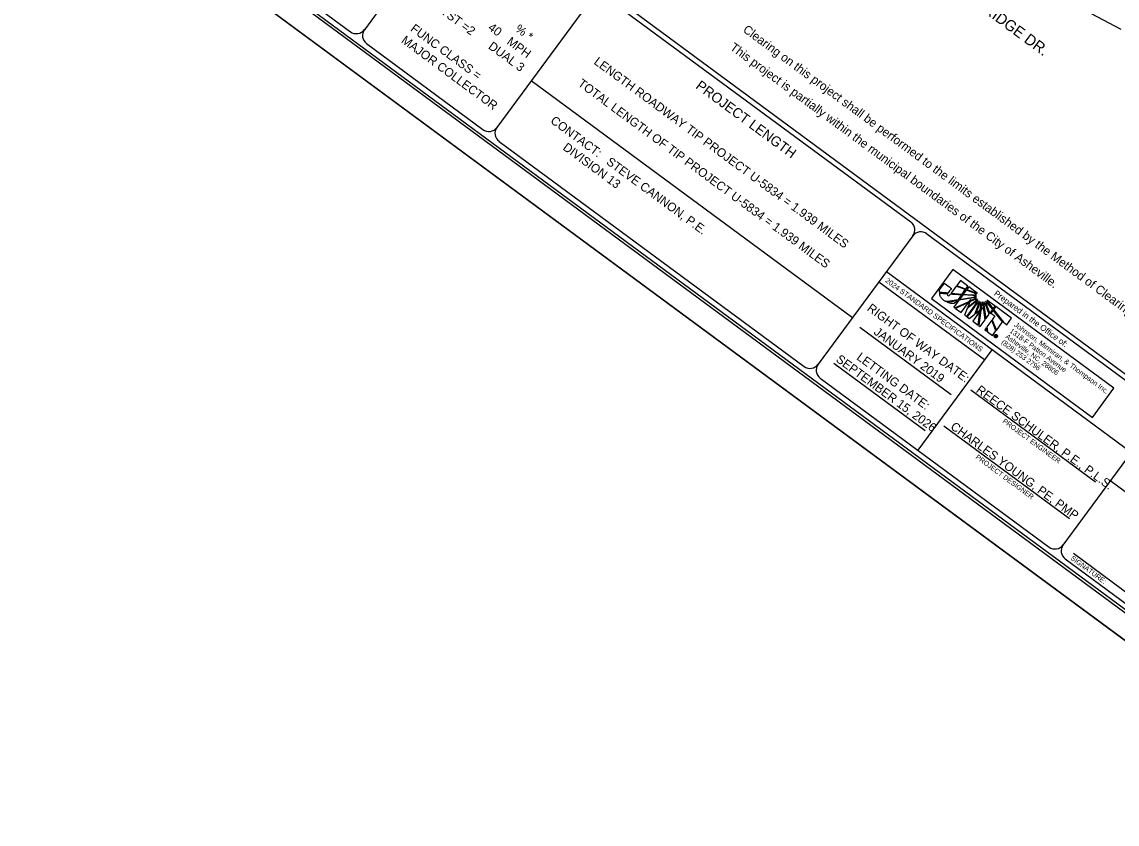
# Model space of a CAD drawing. Extents: x 945666 to 965748, y 644452 to 663300.
# Drawn here: x 945666 to 956642, y 644452 to 652491 of the extents above; entities that cross this region are included whole.
import ezdxf

# ---------------------------------------------------------------- set-up
doc = ezdxf.new("R2010")
doc.units = 0
for name, color, linetype in [('Default', 7, 'Continuous'), ('Old_Level_23', 7, 'Continuous'), ('Sheet Cutting Line CELL', 7, 'Continuous'), ('Sheet Data Field CELL', 7, 'Continuous'), ('Sheet Plan Layout CELL', 7, 'Continuous'), ('Sheet Plot Border Inside CELL', 7, 'Continuous'), ('Sheet Plot Border Outside CELL', 7, 'Continuous'), ('Sheet Title CELL', 7, 'Continuous')]:
    doc.layers.add(name, color=color, linetype=linetype)

msp = doc.modelspace()

# ---------------------------------------------------------------- linework, layer by layer
at = {"layer": 'Default'}
for p, q in [((955071, 649898), (955035, 649848)), ((955147, 649842), (955071, 649898)), ((955030, 649842), (954978, 649772)), ((955121, 649808), (955030, 649842)), ((955035, 649848), (955125, 649813)), ((955089, 649764), (955121, 649808)), ((955131, 649804), (955101, 649763)), ((955125, 649813), (955147, 649842)), ((955207, 649775), (955131, 649804)), ((955155, 649837), (955135, 649810)), ((955135, 649810), (955211, 649781)), ((955240, 649774), (955155, 649837)), ((955234, 649760), (955207, 649775)), ((955211, 649781), (955240, 649774)), ((954978, 649772), (955089, 649764)), ((955055, 649702), (955005, 649633)), ((955017, 649624), (955161, 649690)), ((955153, 649679), (955023, 649620)), ((955202, 649727), (955055, 649702)), ((955096, 649757), (955061, 649710)), ((955061, 649710), (955202, 649734)), ((955080, 649578), (955153, 649679)), ((955192, 649750), (955096, 649757)), ((955101, 649763), (955184, 649757)), ((955221, 649684), (955140, 649618)), ((955145, 649631), (955220, 649692)), ((955166, 649685), (955145, 649631)), ((955161, 649690), (955176, 649710)), ((955210, 649705), (955166, 649685)), ((955169, 649693), (955207, 649711)), ((955176, 649710), (955169, 649693)), ((955184, 649757), (955234, 649760)), ((955232, 649744), (955192, 649750)), ((955202, 649734), (955232, 649744)), ((955234, 649728), (955202, 649727)), ((955207, 649711), (955234, 649728)), ((955209, 649639), (955249, 649701)), ((955239, 649713), (955210, 649705)), ((955262, 649692), (955214, 649635)), ((955220, 649692), (955239, 649713)), ((955249, 649701), (955221, 649684)), ((955254, 649660), (955262, 649692)), ((955276, 649686), (955261, 649660)), ((955277, 649656), (955276, 649686)), ((955292, 649685), (955284, 649654)), ((955301, 649655), (955292, 649685)), ((955308, 649687), (955307, 649656)), ((955326, 649651), (955308, 649687)), ((955323, 649694), (955335, 649645)), ((955344, 649674), (955323, 649694)), ((955420, 649642), (955336, 649704)), ((955336, 649704), (955350, 649678)), ((955396, 649609), (955344, 649674)), ((955350, 649678), (955400, 649614)), ((955005, 649633), (955017, 649624)), ((955023, 649620), (955080, 649578)), ((955140, 649618), (955114, 649553)), ((955135, 649538), (955209, 649639)), ((955214, 649635), (955140, 649534)), ((955161, 649519), (955215, 649561)), ((955268, 649591), (955196, 649493)), ((955215, 649561), (955254, 649660)), ((955261, 649660), (955225, 649569)), ((955225, 649569), (955270, 649606)), ((955250, 649453), (955268, 649591)), ((955276, 649602), (955256, 649448)), ((955270, 649606), (955277, 649656)), ((955293, 649624), (955276, 649602)), ((955284, 649654), (955278, 649612)), ((955278, 649612), (955293, 649624)), ((955319, 649506), (955301, 649655)), ((955307, 649656), (955325, 649514)), ((955325, 649514), (955361, 649562)), ((955361, 649562), (955326, 649651)), ((955335, 649645), (955366, 649569)), ((955366, 649569), (955396, 649609)), ((955400, 649603), (955378, 649572)), ((955378, 649572), (955417, 649544)), ((955400, 649614), (955420, 649642)), ((955401, 649603), (955400, 649603)), ((955493, 649484), (955401, 649603)), ((955426, 649638), (955404, 649609)), ((955404, 649609), (955404, 649608)), ((955404, 649608), (955503, 649481)), ((955585, 649521), (955426, 649638)), ((955114, 649553), (955135, 649538)), ((955140, 649534), (955161, 649519)), ((955196, 649493), (955250, 649453)), ((955256, 649448), (955269, 649438)), ((955269, 649438), (955319, 649506)), ((955385, 649501), (955336, 649434)), ((955427, 649394), (955385, 649501)), ((955417, 649544), (955390, 649507)), ((955390, 649507), (955432, 649400)), ((955432, 649400), (955493, 649484)), ((955503, 649481), (955537, 649456)), ((955537, 649456), (955585, 649521)), ((955330, 649426), (955315, 649405)), ((955315, 649405), (955334, 649391)), ((955334, 649391), (955330, 649426)), ((955336, 649434), (955342, 649385)), ((955342, 649385), (955393, 649347)), ((955393, 649347), (955427, 649394)), ((955418, 649340), (955426, 649352)), ((955421, 649338), (955418, 649340)), ((955424, 649343), (955421, 649338)), ((955426, 649341), (955424, 649343)), ((955427, 649347), (955425, 649345)), ((955425, 649345), (955428, 649343)), ((955426, 649352), (955431, 649348)), ((955428, 649343), (955426, 649341)), ((955426, 649341), (955428, 649343)), ((955426, 649341), (955426, 649341)), ((955430, 649346), (955427, 649347)), ((955428, 649343), (955428, 649343)), ((955431, 649348), (955430, 649346)), ((955430, 649346), (955431, 649348)), ((955430, 649346), (955430, 649346)), ((955431, 649348), (955432, 649348)), ((955436, 649355), (955434, 649352)), ((955434, 649352), (955436, 649355)), ((955419, 649332), (955417, 649329)), ((955417, 649329), (955419, 649332)), ((955418, 649329), (955417, 649329)), ((955419, 649332), (955419, 649332))]:
    msp.add_line(p, q, dxfattribs=at)
msp.add_lwpolyline([(954781, 649718), (956394, 648528), (956609, 648819), (954996, 650009)], close=True, dxfattribs=at)
for points in [[(955035, 649848), (955125, 649813), (955147, 649842), (955071, 649898), (955035, 649848)], [(954978, 649772), (955089, 649764), (955121, 649808), (955030, 649842), (954978, 649772)], [(955131, 649804), (955101, 649763), (955184, 649757), (955234, 649760), (955207, 649775), (955131, 649804)], [(955211, 649781), (955240, 649774), (955155, 649837), (955135, 649810), (955211, 649781)], [(955234, 649728), (955202, 649727), (955055, 649702), (955005, 649633), (955017, 649624), (955161, 649690), (955176, 649710), (955169, 649693), (955207, 649711), (955234, 649728)], [(955023, 649620), (955080, 649578), (955153, 649679), (955023, 649620)], [(955096, 649757), (955061, 649710), (955202, 649734), (955232, 649744), (955192, 649750), (955096, 649757)], [(955221, 649684), (955140, 649618), (955114, 649553), (955135, 649538), (955209, 649639), (955249, 649701), (955221, 649684)], [(955262, 649692), (955214, 649635), (955140, 649534), (955161, 649519), (955215, 649561), (955254, 649660), (955262, 649692)], [(955239, 649713), (955210, 649705), (955166, 649685), (955145, 649631), (955220, 649692), (955239, 649713)], [(955276, 649686), (955261, 649660), (955225, 649569), (955270, 649606), (955277, 649656), (955276, 649686)], [(955292, 649685), (955284, 649654), (955278, 649612), (955293, 649624), (955276, 649602), (955256, 649448), (955269, 649438), (955319, 649506), (955301, 649655), (955292, 649685)], [(955308, 649687), (955307, 649656), (955325, 649514), (955361, 649562), (955326, 649651), (955308, 649687)], [(955323, 649694), (955335, 649645), (955366, 649569), (955396, 649609), (955344, 649674), (955323, 649694)], [(955350, 649678), (955400, 649614), (955420, 649642), (955336, 649704), (955350, 649678)], [(955196, 649493), (955250, 649453), (955268, 649591), (955196, 649493)], [(955401, 649603), (955400, 649603), (955378, 649572), (955417, 649544), (955390, 649507), (955432, 649400), (955493, 649484), (955401, 649603)], [(955585, 649521), (955426, 649638), (955404, 649609), (955404, 649608), (955503, 649481), (955537, 649456), (955585, 649521)], [(955385, 649501), (955336, 649434), (955342, 649385), (955393, 649347), (955427, 649394), (955385, 649501), (955385, 649501)], [(955315, 649405), (955315, 649405), (955334, 649391), (955330, 649426), (955315, 649405)], [(955430, 649336), (955429, 649335), (955429, 649334), (955429, 649334), (955428, 649332), (955426, 649334)]]:
    msp.add_lwpolyline(points, dxfattribs=at)
for points, degree in [([(954981, 649820), (954981, 649820), (954911, 649872), (954911, 649872), (954911, 649872), (954879, 649828), (954879, 649828), (954879, 649828), (954875, 649823), (954875, 649823), (954865, 649810), (954862, 649795), (954863, 649780), (954863, 649780), (954946, 649773), (954947, 649774), (954947, 649774), (954981, 649820), (954981, 649820)], 3), ([(954945, 649749), (954941, 649753), (954939, 649758), (954943, 649767), (954943, 649767), (954864, 649774), (954864, 649774), (954868, 649744), (954887, 649714), (954910, 649697), (954915, 649693), (954920, 649690), (954927, 649687), (954927, 649687), (955047, 649707), (955047, 649707), (955047, 649707), (955085, 649758), (955085, 649758), (955085, 649758), (954974, 649765), (954974, 649765), (954960, 649746), (954951, 649745), (954945, 649749)], 3), ([(954945, 649749), (954941, 649753), (954939, 649758), (954943, 649767), (954943, 649767), (954864, 649774), (954864, 649774), (954868, 649744), (954887, 649714), (954910, 649697), (954915, 649693), (954920, 649690), (954927, 649687), (954927, 649687), (955047, 649707), (955047, 649707), (955047, 649707), (955085, 649758), (955085, 649758), (955085, 649758), (954974, 649765), (954974, 649765), (954960, 649746), (954951, 649745), (954945, 649749)], 3), ([(955041, 649699), (955041, 649699), (954938, 649682), (954938, 649682), (954972, 649668), (955015, 649665), (955041, 649699)], 3), ([(955417, 649329), (955414, 649332), (955412, 649336), (955411, 649340), (955410, 649344), (955411, 649348), (955414, 649352), (955417, 649355), (955420, 649357), (955424, 649358), (955429, 649358), (955433, 649358), (955436, 649355)], 3), ([(955434, 649352), (955432, 649355), (955428, 649355), (955425, 649355), (955422, 649354), (955419, 649353), (955417, 649350), (955415, 649347), (955414, 649344), (955414, 649340), (955415, 649337), (955417, 649334), (955419, 649332)], 3), ([(955419, 649332), (955422, 649330), (955425, 649329), (955429, 649330), (955432, 649330), (955435, 649332), (955437, 649335), (955439, 649337), (955440, 649341), (955440, 649344), (955439, 649348), (955437, 649350), (955434, 649352)], 3), ([(955428, 649339), (955428, 649339), (955427, 649340), (955426, 649341)], 2), ([(955426, 649334), (955426, 649335), (955426, 649336), (955427, 649337), (955428, 649338), (955428, 649339), (955428, 649339)], 3), ([(955428, 649343), (955429, 649342), (955431, 649342), (955431, 649343), (955432, 649343), (955431, 649344), (955430, 649346)], 3), ([(955431, 649339), (955431, 649338), (955431, 649337), (955430, 649336)], 2), ([(955432, 649348), (955435, 649345), (955435, 649343), (955434, 649341), (955433, 649340), (955432, 649339), (955431, 649339)], 3), ([(955436, 649355), (955440, 649352), (955442, 649349), (955443, 649344), (955443, 649340), (955442, 649336), (955440, 649333)], 3), ([(955440, 649333), (955437, 649329), (955434, 649327), (955429, 649326), (955425, 649326), (955421, 649327), (955418, 649329)], 3)]:
    msp.add_open_spline(points, degree=degree, dxfattribs=at)
at = {"layer": 'Sheet Cutting Line CELL'}
msp.add_line((945666, 654448), (959219, 644452), dxfattribs=at)
at = {"layer": 'Sheet Plan Layout CELL'}
msp.add_line((955894, 652835), (956681, 652419), dxfattribs=at)
at = {"layer": 'Sheet Plot Border Inside CELL'}
msp.add_lwpolyline([(945904, 654551), (959316, 644660), (965578, 653151), (952166, 663042)], close=True, dxfattribs=at)
at = {"layer": 'Sheet Plot Border Outside CELL'}
msp.add_lwpolyline([(965748, 653305), (952195, 663300), (945666, 654448), (959219, 644452)], close=True, dxfattribs=at)
at = {"layer": 'Sheet Title CELL'}
for p, q in [((948809, 654801), (960237, 646372)), ((950048, 653701), (949098, 652413)), ((951516, 652742), (954574, 650487)), ((951376, 652721), (950426, 651434)), ((953990, 649526), (950770, 651900)), ((954595, 650347), (953646, 649060)), ((954735, 650368), (957029, 648677)), ((955313, 649104), (954254, 649884)), ((956784, 648177), (954330, 649987)), ((954980, 648754), (954065, 649429)), ((955008, 649329), (955008, 649329)), ((955388, 649206), (954645, 648198)), ((954719, 648393), (953804, 649068)), ((954522, 649092), (954522, 649092)), ((955177, 648803), (956425, 647882)), ((956100, 647249), (957050, 648537)), ((954907, 648443), (956164, 647516)), ((956568, 647899), (958344, 646589)), ((956204, 647166), (957342, 646326))]:
    msp.add_line(p, q, dxfattribs=at)
for points in [[(947239, 653598), (959150, 644814)], [(947711, 653312), (948959, 652392)], [(949120, 652273), (950287, 651413)], [(950448, 651294), (953506, 649038)], [(953667, 648920), (955960, 647228)], [(956121, 647109), (957729, 645924)]]:
    msp.add_lwpolyline(points, dxfattribs=at)
for centre, start, end in [((949018, 652473), 233.5908, 323.5908), ((949179, 652354), 143.5908, 233.5908), ((950346, 651493), 233.5908, 323.5908), ((950507, 651375), 143.5908, 233.5908), ((954515, 650407), 323.5908, 53.5908), ((954676, 650288), 53.5908, 143.5908), ((953565, 649119), 233.5908, 323.5908), ((953726, 649001), 143.5908, 233.5908), ((956020, 647309), 233.5908, 323.5908), ((956181, 647190), 143.5908, 233.5908)]:
    msp.add_arc(centre, 100, start, end, dxfattribs=at)

# ---------------------------------------------------------------- texts
at = {"layer": 'Default'}
for s, height, p in [('Johnson, Mirmiran, & Thompson Inc.', 51.21, (955605, 649445)), ('Asheville, NC, 28806', 49.75, (955518, 649327)), ('1318-F Patton Avenue ', 49.75, (955560, 649384)), ('(828) 253 2796', 49.75, (955476, 649270))]:
    msp.add_text(s, height=height, rotation=323.5908, dxfattribs=at).set_placement(p)
at = {"layer": 'Old_Level_23'}
msp.add_text('ALPINE RIDGE DR.', height=110, rotation=323.5908, dxfattribs=at).set_placement((954839, 652930))
at = {"layer": 'Sheet Data Field CELL'}
for s, p in [('* TTST =2', (949737, 652669)), ('FUNC CLASS =', (949553, 652407)), ('40', (950330, 652418)), ('% *', (950602, 652404)), ('Clearing on this project shall be performed to the limits established by the Method of Clearing II.', (952885, 652397)), ('MAJOR COLLECTOR', (949461, 652290)), ('MPH', (950519, 652277)), ('DUAL 3', (950333, 652230)), ('This project is partially within the municipal boundaries of the City of Asheville.', (952755, 652219)), ('LENGTH ROADWAY TIP PROJECT U-5834 = 1.939 MILES', (951391, 652076)), ('TOTAL LENGTH OF TIP PROJECT U-5834 = 1.939 MILES', (951230, 651857)), ('CONTACT:   STEVE CANNON, P.E.', (950956, 651485)), ('        DIVISION 13 ', (950871, 651371)), ('JANUARY 2019', (954196, 649368)), ('SEPTEMBER 15, 2026', (953817, 649094)), ('REECE SCHULER, P.E., P.L.S.', (955221, 648786)), ('CHARLES YOUNG, PE, PMP', (954965, 648419))]:
    msp.add_text(s, height=87.5, rotation=323.5908, dxfattribs=at).set_placement(p)
at = {"layer": 'Sheet Title CELL'}
for s, height, p in [('PROJECT LENGTH', 100, (952411, 651832)), ('2024 STANDARD SPECIFICATIONS', 52, (954313, 649889)), ('Prepared in the Office of:', 59.99, (955402, 649757)), ('RIGHT OF WAY DATE: ', 87.5, (954129, 649605)), ('LETTING DATE:', 87.5, (954024, 649115)), ('PROJECT ENGINEER', 50, (955489, 648480)), ('PROJECT DESIGNER', 50, (955219, 648120)), ('SIGNATURE:', 50, (956171, 647107))]:
    msp.add_text(s, height=height, rotation=323.5908, dxfattribs=at).set_placement(p)

doc.saveas('drawing.dxf')
